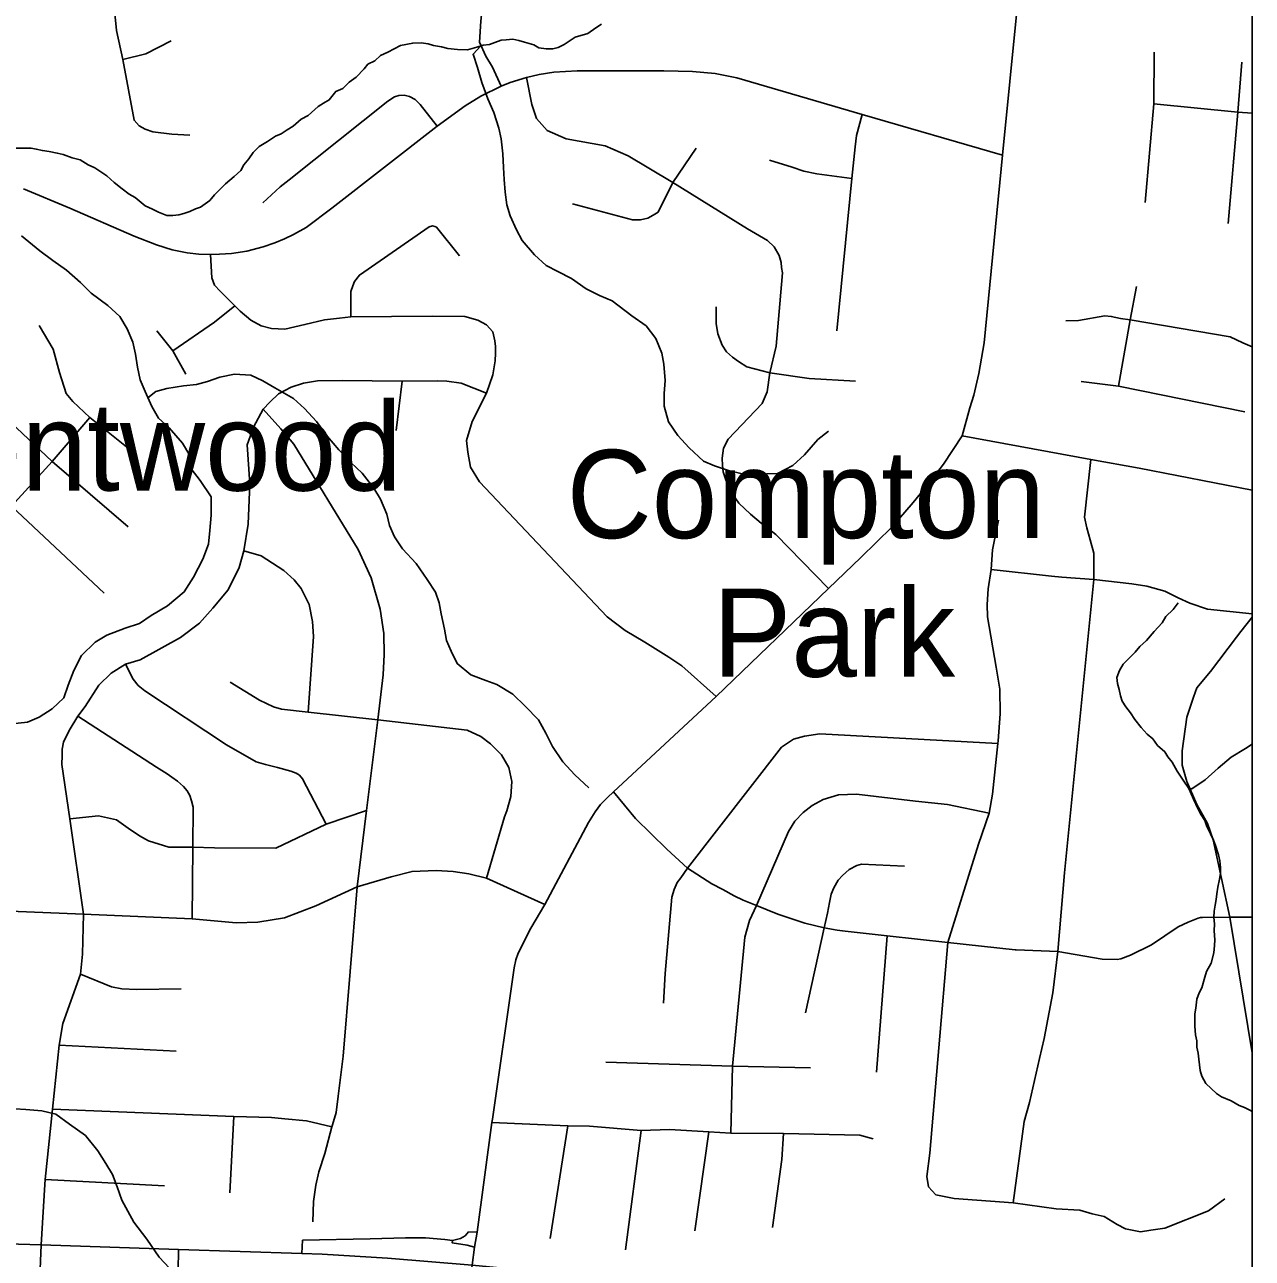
# Model space of a CAD drawing. Extents: x 0 to 34, y 0 to 22.
# Drawn here: x 7.701 to 8.8, y 15.277 to 16.382 of the extents above; entities that cross this region are included whole.
import ezdxf

# ---------------------------------------------------------------- set-up
doc = ezdxf.new("R2010")
doc.units = 0
for name, color, linetype in [('GM_X_County_Road', 7, 'Continuous'), ('GM_X_Interchange_Ramps', 7, 'Continuous'), ('GM_X_Minor_River', 7, 'Continuous'), ('GM_X_State_Route', 7, 'Continuous'), ('GM_X_Township_Subdivision', 7, 'Continuous'), ('GM_X_Unincorporated_Text', 7, 'Continuous'), ('SH_Data', 7, 'Continuous')]:
    doc.layers.add(name, color=color, linetype=linetype)

msp = doc.modelspace()

# ---------------------------------------------------------------- linework, layer by layer
at = {"layer": 'GM_X_County_Road'}
for points in [[(8.54, 16.0139), (8.547, 16.039), (8.5505, 16.0505), (8.5551, 16.0697), (8.5597, 16.0973), (8.5763, 16.2655), (8.5957, 16.4605)], [(7.6994, 16.2351), (7.7409, 16.218), (7.7987, 16.1928), (7.8185, 16.1851), (7.8325, 16.1805), (7.8462, 16.178), (7.8564, 16.1767), (7.867, 16.1764), (7.8751, 16.1766), (7.8859, 16.1772), (7.8996, 16.1794), (7.9141, 16.1833), (7.9246, 16.1868), (7.9333, 16.1905), (7.9412, 16.1943), (7.9527, 16.2007), (7.9755, 16.2178), (8.0699, 16.2915), (8.0949, 16.3097), (8.109, 16.3183), (8.1273, 16.3271), (8.1352, 16.3304), (8.15, 16.335), (8.1613, 16.3376), (8.1746, 16.3398), (8.1955, 16.3408), (8.2731, 16.3408), (8.2986, 16.3403), (8.319, 16.3385), (8.3384, 16.3346), (8.4505, 16.3018), (8.5763, 16.2655)], [(8.2189, 15.6864), (8.2225, 15.69), (8.2279, 15.695), (8.3197, 15.7805), (8.4203, 15.8773), (8.4495, 15.9051), (8.4775, 15.9324), (8.4964, 15.9543), (8.5106, 15.972), (8.5233, 15.9886), (8.54, 16.0139)], [(8.54, 16.0139), (8.6554, 15.9928), (8.6988, 15.985), (8.8, 15.9653)], [(8.1194, 15.402), (8.1388, 15.5375), (8.1403, 15.5447), (8.1424, 15.5507), (8.1538, 15.573), (8.1663, 15.5941), (8.2056, 15.6677), (8.2115, 15.6772), (8.2161, 15.6837), (8.2189, 15.6864)], [(8.0892, 15.1724), (8.0893, 15.1794), (8.0906, 15.2033), (8.0943, 15.2247), (8.1014, 15.2712), (8.1035, 15.2873), (8.1057, 15.3008), (8.119, 15.3989), (8.1194, 15.402)]]:
    msp.add_lwpolyline(points, dxfattribs=at)
at = {"layer": 'GM_X_Interchange_Ramps'}
for points in [[(8.1057, 15.3008), (8.0981, 15.3011), (8.095, 15.2975), (8.0909, 15.295), (8.0836, 15.2933), (8.0767, 15.2941), (8.0595, 15.2956), (8.0416, 15.2956), (8.01, 15.2948), (7.9495, 15.2935), (7.9488, 15.2816)], [(8.1035, 15.2873), (8.0968, 15.2891), (8.0834, 15.2912), (8.0836, 15.2933)], [(7.8384, 15.2853), (7.8379, 15.2661), (7.8559, 15.2647), (7.8926, 15.2565), (8.0725, 15.212), (8.076, 15.2105), (8.0783, 15.2085), (8.0807, 15.2042), (8.0906, 15.2033)]]:
    msp.add_lwpolyline(points, dxfattribs=at)
at = {"layer": 'GM_X_Minor_River'}
for points in [[(8.217, 16.3827), (8.212, 16.3794), (8.205, 16.3743), (8.1935, 16.3712), (8.1838, 16.3646), (8.1784, 16.3617), (8.1735, 16.3607), (8.1677, 16.3605), (8.1609, 16.3614), (8.1564, 16.3642), (8.1481, 16.3667), (8.1432, 16.368), (8.1376, 16.3693), (8.1318, 16.3687), (8.1273, 16.3685), (8.1215, 16.3663), (8.1169, 16.3646), (8.1112, 16.364), (8.1054, 16.3622), (8.097, 16.3598), (8.0883, 16.36), (8.0795, 16.361), (8.0739, 16.3623), (8.0667, 16.3637), (8.0618, 16.365), (8.0557, 16.3659), (8.0481, 16.3657), (8.037, 16.3637), (8.0258, 16.3576), (8.0193, 16.3547), (8.0142, 16.3499), (8.008, 16.347), (8.0045, 16.3426), (7.9974, 16.3351), (7.9912, 16.3307), (7.9854, 16.3252), (7.9792, 16.3223), (7.9733, 16.3149), (7.9683, 16.312), (7.9633, 16.3091), (7.9543, 16.3009), (7.9481, 16.2977), (7.9411, 16.2914), (7.9357, 16.2881), (7.9303, 16.2845), (7.9253, 16.2823), (7.9179, 16.2776), (7.9106, 16.2732), (7.9051, 16.2677), (7.9012, 16.2621), (7.8968, 16.2568), (7.894, 16.2516), (7.8882, 16.2464), (7.8804, 16.2398), (7.8749, 16.2342), (7.8706, 16.2298), (7.8663, 16.2249), (7.8581, 16.2187)], [(8.1092, 16.3634), (8.1022, 16.3558), (8.1061, 16.3439), (8.11, 16.3305), (8.1153, 16.3159), (8.1207, 16.3036), (8.1253, 16.2895), (8.1274, 16.2799), (8.1289, 16.2666), (8.1294, 16.2544), (8.1299, 16.2437), (8.1308, 16.2323), (8.1324, 16.2208), (8.1352, 16.2109), (8.141, 16.1986), (8.1461, 16.1889), (8.1571, 16.1761), (8.1676, 16.1667), (8.1781, 16.1611), (8.1904, 16.1548), (8.2035, 16.1457), (8.2155, 16.1397), (8.2268, 16.1349), (8.2444, 16.1215), (8.2571, 16.1124), (8.2659, 16.1012), (8.2713, 16.0881), (8.2729, 16.0782), (8.2741, 16.0637), (8.2734, 16.0519), (8.2732, 16.0405), (8.277, 16.0264), (8.2854, 16.0144), (8.2958, 16.0031), (8.3084, 15.9914), (8.3182, 15.987), (8.331, 15.9828), (8.3431, 15.9799), (8.353, 15.9793), (8.3648, 15.9801), (8.3747, 15.9802), (8.3885, 15.9875), (8.399, 15.9971), (8.4108, 16.0106), (8.4204, 16.0183)], [(7.7063, 16.2717), (7.6879, 16.2716)], [(7.8581, 16.2187), (7.8535, 16.2173), (7.8485, 16.2148), (7.8432, 16.213), (7.8386, 16.212), (7.8332, 16.2114), (7.8279, 16.2112), (7.8204, 16.2144), (7.8151, 16.2169), (7.8084, 16.2201), (7.7994, 16.2276), (7.7942, 16.2304), (7.7879, 16.2351), (7.7808, 16.241), (7.7741, 16.2469), (7.7633, 16.2541), (7.7573, 16.2566), (7.7502, 16.2613), (7.743, 16.2631), (7.7351, 16.2659), (7.7298, 16.2672), (7.7226, 16.2686), (7.7165, 16.2695), (7.7109, 16.2708), (7.7063, 16.2717)], [(7.6977, 16.193), (7.7141, 16.1797), (7.7257, 16.171), (7.738, 16.1624), (7.7507, 16.1514), (7.76, 16.1417), (7.7749, 16.1307), (7.7857, 16.1209), (7.7922, 16.1097), (7.7973, 16.0978), (7.7997, 16.0871), (7.8017, 16.0756), (7.804, 16.0642), (7.8084, 16.0538), (7.8145, 16.0403), (7.8203, 16.0299), (7.83, 16.0213), (7.8418, 16.0073), (7.8484, 15.9965), (7.8496, 15.9843), (7.8577, 15.9739), (7.8676, 15.9595), (7.8676, 15.9428), (7.8665, 15.9291), (7.8651, 15.917), (7.8602, 15.9034), (7.8518, 15.8873), (7.8435, 15.8742), (7.8284, 15.8616), (7.8137, 15.8532), (7.8033, 15.8459), (7.7907, 15.8416), (7.7742, 15.8355), (7.7638, 15.8293), (7.7513, 15.8171), (7.7445, 15.8039), (7.7396, 15.7908), (7.7356, 15.7794), (7.7251, 15.7694), (7.7135, 15.7621), (7.7031, 15.7574), (7.689, 15.7559)], [(7.811, 16.0481), (7.8179, 16.0536), (7.8278, 16.0564), (7.8427, 16.0587), (7.8545, 16.0599), (7.8644, 16.0627), (7.8752, 16.0666), (7.8885, 16.0693), (7.903, 16.0682), (7.9139, 16.0634), (7.9247, 16.057), (7.9412, 16.0475), (7.9512, 16.0385), (7.962, 16.0268), (7.9719, 16.0133), (7.9819, 16.0016), (7.9926, 15.99), (8.0027, 15.9806), (8.0133, 15.967), (8.0192, 15.9574), (8.0249, 15.9439), (8.0274, 15.9336), (8.0317, 15.9236), (8.039, 15.9128), (8.0512, 15.8995), (8.0611, 15.8852), (8.0685, 15.874), (8.0717, 15.8644), (8.0737, 15.8545), (8.0764, 15.8407), (8.0784, 15.8308), (8.0824, 15.8212), (8.0878, 15.81), (8.1001, 15.7998), (8.1137, 15.7949), (8.1234, 15.7913), (8.1377, 15.7826), (8.1488, 15.772), (8.1607, 15.7596), (8.1672, 15.7476), (8.1734, 15.7357), (8.1826, 15.7221), (8.1933, 15.7105), (8.2059, 15.6987)], [(8.7335, 15.8644), (8.7291, 15.8585), (8.7225, 15.8522), (8.7193, 15.8466), (8.7122, 15.8388), (8.7052, 15.8306), (8.6993, 15.8254), (8.695, 15.8202), (8.6907, 15.8158), (8.6844, 15.8095), (8.6809, 15.8038), (8.6788, 15.7974), (8.6794, 15.7921), (8.6808, 15.7867), (8.6818, 15.781), (8.6835, 15.7764), (8.6868, 15.7713), (8.6909, 15.7659), (8.6949, 15.76), (8.7004, 15.7527), (8.7059, 15.7468), (8.7108, 15.7425), (8.7152, 15.7366), (8.7215, 15.7311), (8.7244, 15.7265), (8.7281, 15.7218), (8.7328, 15.7137), (8.7386, 15.7047), (8.743, 15.6981), (8.7473, 15.6885), (8.7516, 15.6796), (8.7542, 15.6746), (8.7575, 15.6696), (8.7592, 15.6642), (8.7625, 15.6576), (8.7653, 15.6518), (8.7671, 15.6472), (8.7696, 15.6388), (8.7709, 15.6334), (8.7715, 15.6273), (8.7714, 15.622), (8.7705, 15.617), (8.7691, 15.6098), (8.7682, 15.6038), (8.7677, 15.5988), (8.7668, 15.5935), (8.7659, 15.5882), (8.7654, 15.5825), (8.766, 15.5768), (8.7658, 15.5707), (8.7663, 15.5627), (8.7662, 15.5574), (8.7656, 15.5509), (8.7631, 15.5418), (8.7591, 15.5343), (8.7574, 15.529), (8.7549, 15.5196), (8.7525, 15.5151), (8.7504, 15.5094), (8.7495, 15.5015), (8.7486, 15.4962), (8.7484, 15.4901), (8.7486, 15.4851), (8.7492, 15.4775), (8.7502, 15.4721), (8.7504, 15.4664), (8.7514, 15.461), (8.752, 15.4557), (8.7527, 15.4507), (8.7533, 15.4454), (8.7547, 15.4404), (8.7583, 15.4338), (8.7679, 15.4248), (8.7724, 15.422), (8.7811, 15.4183), (8.7882, 15.4143), (8.7931, 15.4123), (8.7983, 15.4098), (8.8, 15.4089)], [(8.7432, 15.6977), (8.7459, 15.6977), (8.7579, 15.7058), (8.7695, 15.7162), (8.7812, 15.7261), (8.7939, 15.7338), (8.8, 15.7377)], [(7.6916, 15.4112), (7.7015, 15.4106), (7.7159, 15.4095), (7.7284, 15.4065), (7.7407, 15.3975), (7.7549, 15.3872), (7.766, 15.3736), (7.7733, 15.3621), (7.7791, 15.3524), (7.7834, 15.3413), (7.7877, 15.3294), (7.7928, 15.3194), (7.7982, 15.3097), (7.81, 15.2946), (7.821, 15.2784), (7.8303, 15.2686)]]:
    msp.add_lwpolyline(points, dxfattribs=at)
at = {"layer": 'GM_X_State_Route'}
msp.add_lwpolyline([(7.375, 15.3384), (7.3915, 15.3291), (7.4204, 15.3166), (7.4471, 15.3074), (7.4931, 15.2985), (7.5414, 15.2945), (7.7154, 15.2893), (7.8384, 15.2853), (7.9488, 15.2816), (7.9669, 15.2811), (8.0254, 15.2774), (8.1014, 15.2712), (8.1295, 15.2684), (8.2078, 15.2595), (8.2788, 15.2497), (8.3376, 15.2408), (8.412, 15.227), (8.4869, 15.2128), (8.558, 15.1957), (8.6387, 15.1753)], dxfattribs=at)
at = {"layer": 'GM_X_Township_Subdivision'}
for points in [[(8.1273, 16.3271), (8.1195, 16.3443), (8.1136, 16.354), (8.1078, 16.3666), (8.1092, 16.3855), (8.1158, 16.4501), (8.1129, 16.4965), (8.1033, 16.5259), (8.1016, 16.5346), (8.1013, 16.5541), (8.0996, 16.569), (8.0927, 16.5785)], [(7.7804, 16.4291), (7.7813, 16.3924), (7.7827, 16.3769), (7.7884, 16.3511), (7.7985, 16.2967), (7.8031, 16.2916), (7.8086, 16.2887), (7.8152, 16.2864), (7.8322, 16.2841), (7.8486, 16.2832)], [(7.7884, 16.3511), (7.8092, 16.356), (7.8318, 16.3678)], [(8.7122, 16.3576), (8.7119, 16.3113), (8.7041, 16.2229)], [(8.7784, 16.2041), (8.787, 16.304), (8.7906, 16.3486)], [(8.4203, 15.8773), (8.3733, 15.9257), (8.3601, 15.9359), (8.3507, 15.9439), (8.34, 15.9538), (8.3354, 15.9605), (8.331, 15.9685), (8.3286, 15.9745), (8.3262, 15.9818), (8.3254, 15.9873), (8.3251, 15.9939), (8.3264, 16.003), (8.3307, 16.0109), (8.3611, 16.043), (8.3654, 16.0533), (8.3679, 16.0703), (8.3735, 16.0943), (8.3783, 16.1496), (8.3792, 16.1599), (8.3783, 16.1649), (8.378, 16.1691), (8.3762, 16.1756), (8.3719, 16.1832), (8.3657, 16.189), (8.3479, 16.1995), (8.2811, 16.2409), (8.2596, 16.2537), (8.2409, 16.2647), (8.2204, 16.2736), (8.1856, 16.2801), (8.1684, 16.2875), (8.1589, 16.2982), (8.1548, 16.3109), (8.15, 16.335)], [(8.0699, 16.2915), (8.0546, 16.3109), (8.0504, 16.3152), (8.0451, 16.3178), (8.0403, 16.3192), (8.0356, 16.3189), (8.0318, 16.3176), (8.0259, 16.3137), (7.9375, 16.2432), (7.9295, 16.2371), (7.9138, 16.2226)], [(8.7119, 16.3113), (8.787, 16.304), (8.8, 16.3029)], [(8.4505, 16.3018), (8.4455, 16.283), (8.4443, 16.2728), (8.4414, 16.2444), (8.4278, 16.1081)], [(8.1913, 16.2217), (8.245, 16.2076), (8.2521, 16.2076), (8.2586, 16.2089), (8.2633, 16.2115), (8.2678, 16.2144), (8.2811, 16.2409), (8.302, 16.2717)], [(8.3675, 16.2608), (8.3878, 16.2546), (8.3984, 16.251), (8.41, 16.2487), (8.4414, 16.2444)], [(7.9926, 16.1206), (7.9927, 16.1432), (7.9944, 16.1484), (7.9958, 16.1523), (8.0003, 16.1579), (8.0627, 16.2013), (8.0657, 16.202), (8.0678, 16.2016), (8.0695, 16.2008), (8.0901, 16.1751)], [(8.3197, 15.7805), (8.2892, 15.808), (8.2775, 15.8157), (8.2561, 15.8292), (8.2383, 15.8397), (8.2221, 15.852), (8.108, 15.9728), (8.0997, 15.9858), (8.0975, 15.9993), (8.0963, 16.0098), (8.1014, 16.0269), (8.1142, 16.0523), (8.1199, 16.0686), (8.1219, 16.0813), (8.1223, 16.088), (8.1221, 16.0939), (8.1215, 16.0992), (8.1197, 16.107), (8.1143, 16.1134), (8.1063, 16.1177), (8.0948, 16.1209), (8.0656, 16.1211), (7.9926, 16.1206), (7.9824, 16.1195), (7.9691, 16.1179), (7.9515, 16.1136), (7.9335, 16.1094), (7.9216, 16.1102), (7.9125, 16.1126), (7.9032, 16.1175), (7.8934, 16.1256), (7.8888, 16.1304), (7.8756, 16.1435), (7.8706, 16.149), (7.8681, 16.1556), (7.867, 16.1764)], [(7.7932, 15.9326), (7.7253, 15.9911), (7.6771, 16.036), (7.6695, 16.0455), (7.6608, 16.0579), (7.6529, 16.0736), (7.6476, 16.0883), (7.6459, 16.1058), (7.6452, 16.1249), (7.6467, 16.1474), (7.6477, 16.157), (7.6411, 16.1581), (7.6234, 16.1597)], [(8.6964, 16.1478), (8.6906, 16.1178), (8.6802, 16.0586)], [(7.8333, 16.0902), (7.8706, 16.1157), (7.8888, 16.1304)], [(8.3198, 16.1296), (8.3197, 16.1146), (8.3212, 16.1054), (8.3251, 16.0951), (8.3291, 16.0893), (8.3345, 16.0844), (8.3398, 16.0805), (8.3473, 16.0759), (8.3679, 16.0703), (8.4032, 16.0654), (8.4447, 16.0631)], [(8.633, 16.117), (8.6442, 16.1173), (8.6679, 16.1214), (8.6737, 16.1209), (8.6818, 16.1191), (8.6906, 16.1178), (8.7801, 16.1027), (8.7916, 16.0974), (8.8, 16.0936)], [(7.7917, 16.004), (7.7588, 16.0303), (7.7436, 16.0448), (7.7378, 16.0519), (7.7318, 16.0706), (7.726, 16.0916), (7.7135, 16.1127)], [(7.845, 16.0692), (7.8333, 16.0902), (7.8189, 16.1081)], [(7.7187, 15.3435), (7.719, 15.3478), (7.7256, 15.4109), (7.7315, 15.4683), (7.7346, 15.4877), (7.7506, 15.5319), (7.7524, 15.5498), (7.7531, 15.5855), (7.7411, 15.6709), (7.7337, 15.7197), (7.734, 15.7278), (7.7341, 15.7333), (7.7353, 15.7396), (7.7403, 15.7502), (7.7483, 15.7628), (7.7547, 15.7715), (7.7671, 15.7908), (7.7779, 15.8013), (7.791, 15.8094), (7.8041, 15.8135), (7.8402, 15.8333), (7.8571, 15.8461), (7.8691, 15.8595), (7.8828, 15.8761), (7.8927, 15.8962), (7.8967, 15.9111), (7.9006, 15.9348), (7.9022, 15.9711), (7.8999, 16.0058), (7.9055, 16.0219), (7.9141, 16.0379), (7.92, 16.0442), (7.9279, 16.0515), (7.9391, 16.0575), (7.9502, 16.0612), (7.9629, 16.0632), (7.9848, 16.0636), (8.0385, 16.063), (8.0699, 16.0632), (8.0787, 16.063), (8.0914, 16.0611), (8.1142, 16.0523)], [(8.0334, 16.0189), (8.0385, 16.063)], [(8.6466, 16.0628), (8.6802, 16.0586), (8.7934, 16.0354)], [(7.9762, 15.397), (7.9796, 15.4079), (7.9814, 15.4225), (7.9857, 15.4585), (7.9983, 15.6101), (8.0067, 15.6783), (8.0167, 15.7595), (8.0217, 15.7998), (8.0226, 15.8181), (8.0221, 15.837), (8.0189, 15.8587), (8.0108, 15.8869), (7.9993, 15.9121), (7.9415, 16.0066), (7.9299, 16.0204), (7.9141, 16.0379)], [(7.6489, 15.9085), (7.6888, 15.9511), (7.7253, 15.9911), (7.7588, 16.0303)], [(8.5857, 15.3269), (8.5958, 15.3998), (8.6004, 15.4168), (8.6095, 15.4562), (8.6135, 15.4741), (8.6213, 15.5151), (8.6259, 15.552), (8.6319, 15.6225), (8.658, 15.8854), (8.6582, 15.8987), (8.6582, 15.9088), (8.6547, 15.9207), (8.6519, 15.9315), (8.6498, 15.941), (8.6554, 15.9928)], [(7.7717, 15.8732), (7.6888, 15.9511), (7.6405, 15.9885)], [(8.5728, 15.9384), (8.5674, 15.9119), (8.5662, 15.8942), (8.5634, 15.877), (8.5625, 15.8629), (8.5627, 15.8519), (8.5707, 15.8068), (8.574, 15.787), (8.5742, 15.765), (8.5724, 15.7407), (8.5721, 15.7385), (8.5672, 15.6929), (8.5642, 15.6759), (8.5549, 15.6483), (8.5274, 15.5602), (8.5111, 15.3715), (8.5084, 15.3507), (8.51, 15.3414), (8.5166, 15.3342), (8.5329, 15.331)], [(7.9545, 15.7666), (7.9591, 15.8343), (7.9584, 15.8476), (7.9552, 15.8628), (7.9481, 15.8773), (7.9418, 15.885), (7.9327, 15.8935), (7.9125, 15.9066), (7.8967, 15.9111)], [(8.5662, 15.8942), (8.62, 15.8882), (8.6293, 15.8875)], [(8.6293, 15.8875), (8.658, 15.8854), (8.6922, 15.8815), (8.7054, 15.8793), (8.7215, 15.875), (8.7336, 15.869), (8.744, 15.8642), (8.7599, 15.8588), (8.8, 15.8547)], [(8.8, 15.8515), (8.7897, 15.8388)], [(8.7897, 15.8388), (8.7858, 15.8338), (8.7625, 15.803), (8.7504, 15.7884), (8.7474, 15.78), (8.7412, 15.7619), (8.7371, 15.7318), (8.7372, 15.719), (8.7414, 15.7045), (8.7504, 15.6838), (8.7599, 15.6668), (8.7649, 15.6522), (8.7799, 15.5828), (8.8, 15.4615)], [(7.791, 15.8094), (7.7977, 15.796), (7.8021, 15.7905), (7.8083, 15.7857), (7.8814, 15.7371), (7.9078, 15.722), (7.9161, 15.7197), (7.9271, 15.7169), (7.9388, 15.7137), (7.9437, 15.7118), (7.9466, 15.71), (7.9494, 15.7068), (7.9706, 15.6663)], [(8.1141, 15.6178), (8.1303, 15.6727), (8.1323, 15.6782), (8.1359, 15.6911), (8.1368, 15.7044), (8.1342, 15.717), (8.1275, 15.7284), (8.1178, 15.738), (8.1091, 15.7446), (8.0967, 15.7504), (8.0167, 15.7595), (7.9545, 15.7666), (7.9307, 15.7693), (7.9235, 15.7713), (7.911, 15.7771), (7.8847, 15.7933)], [(7.7483, 15.7628), (7.8187, 15.7171), (7.8282, 15.7114), (7.8324, 15.7084), (7.8374, 15.7048), (7.8429, 15.6998), (7.8461, 15.696), (7.8485, 15.6917), (7.8499, 15.687), (7.8514, 15.6813), (7.8511, 15.6456), (7.8505, 15.5815)], [(8.2727, 15.5057), (8.2742, 15.5325), (8.28, 15.6007), (8.2822, 15.6077), (8.2849, 15.6138), (8.2882, 15.6181), (8.2942, 15.6268), (8.3784, 15.7352), (8.3891, 15.7423), (8.399, 15.7449), (8.4126, 15.747), (8.5721, 15.7385)], [(8.2279, 15.695), (8.2476, 15.6713), (8.2757, 15.6437), (8.2942, 15.6268), (8.316, 15.6128), (8.3257, 15.6076), (8.336, 15.602), (8.344, 15.598), (8.3559, 15.5933), (8.3751, 15.5855), (8.3991, 15.5775), (8.4165, 15.5732), (8.4283, 15.5713), (8.4355, 15.5702), (8.4731, 15.5661), (8.5274, 15.5602), (8.5875, 15.5537), (8.5884, 15.5537)], [(8.333, 15.3895), (8.3345, 15.4494), (8.3454, 15.5649), (8.3496, 15.58), (8.3559, 15.5933), (8.3846, 15.6595), (8.3903, 15.6689), (8.3977, 15.6767), (8.4057, 15.683), (8.4157, 15.6882), (8.4293, 15.6925), (8.4454, 15.6929), (8.4985, 15.6867), (8.5269, 15.6838), (8.5642, 15.6759)], [(7.7411, 15.6709), (7.7666, 15.6735), (7.7827, 15.6702), (7.7931, 15.6626), (7.8033, 15.6556), (7.8116, 15.6511), (7.8297, 15.6456), (7.8511, 15.6456), (7.8705, 15.6449), (7.9256, 15.6448), (7.9706, 15.6663), (8.0067, 15.6783)], [(7.6247, 15.5879), (7.6581, 15.5895), (7.7531, 15.5855), (7.8505, 15.5815), (7.89, 15.5779), (7.9094, 15.5785), (7.9333, 15.5824), (7.9612, 15.593), (7.9983, 15.6101), (8.0287, 15.619), (8.0475, 15.6239), (8.069, 15.6248), (8.0844, 15.6239), (8.0983, 15.6218), (8.1141, 15.6178), (8.1663, 15.5941)], [(8.3998, 15.4972), (8.4165, 15.5732), (8.4194, 15.5865), (8.4212, 15.5959), (8.4228, 15.6036), (8.4251, 15.6092), (8.4291, 15.6159), (8.4331, 15.6201), (8.4361, 15.6228), (8.439, 15.6255), (8.4458, 15.629), (8.45, 15.6303), (8.4884, 15.6285)], [(8.5884, 15.5537), (8.6259, 15.552), (8.6655, 15.5453), (8.6791, 15.5451), (8.6821, 15.5456), (8.6909, 15.5488), (8.7096, 15.5581), (8.7337, 15.5742), (8.7424, 15.5783), (8.7515, 15.5819), (8.7535, 15.5825), (8.7545, 15.5827), (8.7554, 15.5827), (8.7799, 15.5828), (8.8, 15.583)], [(8.4634, 15.4441), (8.4731, 15.5661)], [(7.7506, 15.5319), (7.7783, 15.5206), (7.7877, 15.5186), (7.801, 15.5181), (7.8408, 15.5188)], [(7.7315, 15.4683), (7.8361, 15.463)], [(8.221, 15.453), (8.3345, 15.4494), (8.4042, 15.4478)], [(7.7256, 15.4109), (7.8879, 15.4043), (7.9216, 15.4033), (7.9334, 15.4023), (7.9529, 15.4005), (7.9757, 15.3951)], [(7.8879, 15.4043), (7.8843, 15.3361)], [(7.9587, 15.31), (7.9591, 15.3281), (7.9612, 15.3428), (7.9641, 15.3548), (7.9695, 15.3711), (7.9757, 15.3951), (7.9762, 15.397)], [(8.119, 15.3989), (8.1871, 15.3959), (8.2065, 15.3958), (8.2527, 15.3919), (8.2781, 15.3926), (8.3132, 15.3906), (8.333, 15.3895), (8.38, 15.389), (8.4484, 15.3877), (8.4605, 15.3842)], [(8.1713, 15.2951), (8.1871, 15.3959)], [(8.2385, 15.2848), (8.2527, 15.3919)], [(8.3008, 15.302), (8.3132, 15.3906)], [(8.3704, 15.305), (8.3786, 15.3659), (8.38, 15.389)], [(7.7139, 15.2531), (7.7154, 15.2893), (7.7187, 15.3435)], [(7.719, 15.3478), (7.8257, 15.3423)], [(8.7754, 15.3307), (8.7608, 15.3198), (8.7215, 15.3044), (8.709, 15.3024), (8.7, 15.3009), (8.6864, 15.3038), (8.679, 15.3077), (8.6672, 15.3148), (8.6567, 15.3173), (8.6455, 15.3203), (8.6244, 15.3215), (8.5857, 15.3269), (8.5329, 15.331)]]:
    msp.add_lwpolyline(points, dxfattribs=at)
at = {"layer": 'SH_Data'}
msp.add_line((8.8, 21), (8.8, 14.2), dxfattribs=at)

# ---------------------------------------------------------------- texts
at = {"layer": 'GM_X_Unincorporated_Text'}
for s, p in [('Brentwood', (7.5334, 15.9649)), ('Compton', (8.1859, 15.9224)), ('Park', (8.3167, 15.7982))]:
    msp.add_text(s, height=0.07898, rotation=0, dxfattribs=at).set_placement(p)

doc.saveas('drawing.dxf')
